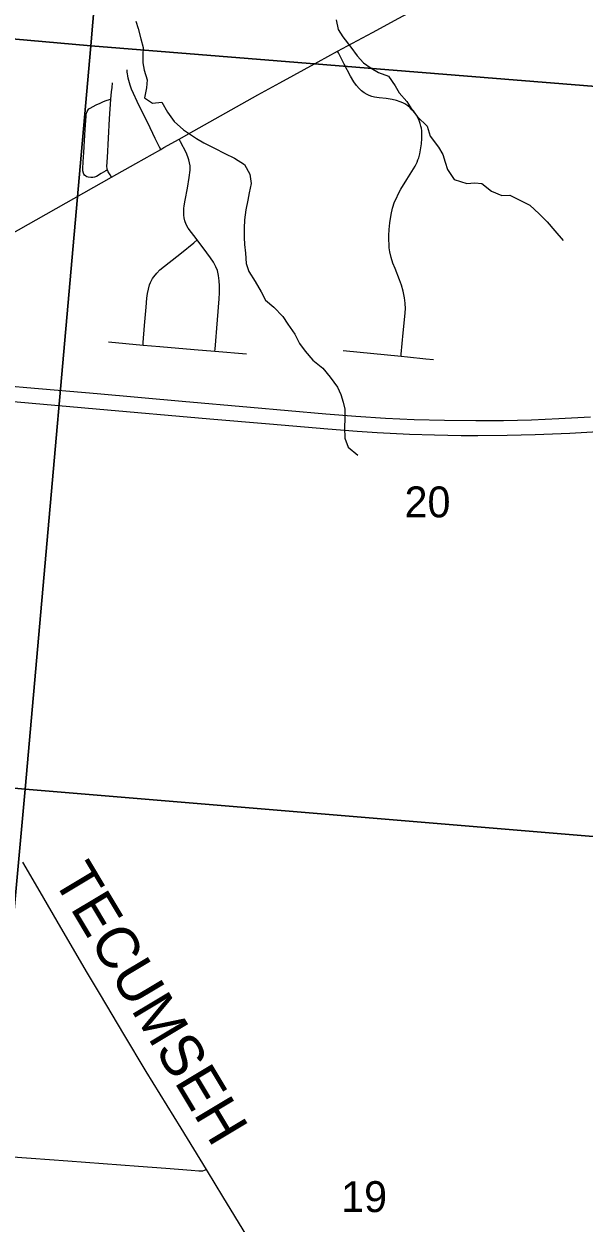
# Model space of a CAD drawing. Extents: x 0 to 34, y 0 to 22.
# Drawn here: x 4.873 to 5.632, y 14.717 to 16.342 of the extents above; entities that cross this region are included whole.
import ezdxf

# ---------------------------------------------------------------- set-up
doc = ezdxf.new("R2010")
doc.units = 0
for name, color, linetype in [('GM_X_County_Road', 7, 'Continuous'), ('GM_X_County_Road_Text', 7, 'Continuous'), ('GM_X_Interstate_Route', 7, 'Continuous'), ('GM_X_Minor_River', 7, 'Continuous'), ('GM_X_Section', 7, 'Continuous'), ('GM_X_Section_Text', 7, 'Continuous'), ('GM_X_Township_Road', 7, 'Continuous')]:
    doc.layers.add(name, color=color, linetype=linetype)

msp = doc.modelspace()

# ---------------------------------------------------------------- linework, layer by layer
at = {"layer": 'GM_X_County_Road'}
for points in [[(5.2978, 16.3047), (5.3453, 16.3303), (5.3808, 16.3494), (5.4408, 16.3822), (5.4842, 16.4065), (5.5036, 16.4175)], [(5.0832, 16.1858), (5.1029, 16.1969), (5.1463, 16.2213), (5.1897, 16.2455), (5.2196, 16.2621), (5.2714, 16.2904), (5.2978, 16.3047)], [(5.0582, 16.1717), (5.0623, 16.1741), (5.0832, 16.1858)], [(4.9914, 16.134), (5.0244, 16.1527), (5.0582, 16.1717)], [(4.6243, 15.9265), (4.652, 15.9425), (4.7017, 15.9701), (4.7345, 15.9885), (4.7768, 16.0126), (4.8276, 16.0414), (4.9914, 16.134)], [(5.1201, 14.7896), (5.0857, 14.8456), (5.0386, 14.9224), (5.0079, 14.9728), (4.9922, 14.9996), (4.9765, 15.0264), (4.9588, 15.0557), (4.9257, 15.1119), (4.8918, 15.1712), (4.8713, 15.206)], [(5.2834, 14.3675), (5.2817, 14.3768), (5.2809, 14.3811), (5.2799, 14.387), (5.2791, 14.3933), (5.2745, 14.4397), (5.2709, 14.4768), (5.268, 14.5046), (5.2659, 14.5201), (5.2641, 14.5293), (5.2617, 14.5383), (5.2601, 14.5434), (5.2586, 14.5472), (5.2561, 14.553), (5.252, 14.5613), (5.24, 14.5832), (5.2296, 14.6022), (5.1983, 14.6594), (5.1845, 14.6838), (5.175, 14.6998), (5.1587, 14.7263), (5.1425, 14.7528), (5.1216, 14.7873), (5.1201, 14.7896)]]:
    msp.add_lwpolyline(points, dxfattribs=at)
at = {"layer": 'GM_X_Interstate_Route'}
for points in [[(4.4694, 15.8846), (4.5389, 15.8785), (4.5509, 15.8774), (4.6352, 15.8704), (4.8152, 15.8545), (4.8766, 15.8491), (4.9718, 15.8409), (5.087, 15.8306), (5.1797, 15.8225), (5.282, 15.8136), (5.3227, 15.8103), (5.3626, 15.8077), (5.4014, 15.806), (5.4428, 15.8049), (5.4852, 15.8044), (5.5227, 15.8046), (5.5606, 15.8054), (5.5978, 15.807), (5.6405, 15.8094)], [(4.4701, 15.8638), (4.5074, 15.8606), (4.5483, 15.8571), (4.639, 15.8493), (4.7133, 15.8429), (4.8636, 15.8295), (4.9707, 15.8203), (5.1248, 15.8069), (5.2055, 15.7999), (5.2844, 15.7931), (5.3244, 15.7899), (5.3512, 15.7881), (5.3951, 15.7859), (5.4291, 15.7849), (5.4653, 15.7843), (5.4878, 15.7839), (5.5274, 15.7845), (5.5654, 15.7855), (5.6127, 15.7873), (5.6507, 15.7897)]]:
    msp.add_lwpolyline(points, dxfattribs=at)
at = {"layer": 'GM_X_Minor_River'}
for points in [[(5.0242, 16.3454), (5.0275, 16.3355), (5.0311, 16.3217), (5.0344, 16.3096), (5.0339, 16.2997), (5.0338, 16.2891), (5.0355, 16.2792), (5.0399, 16.2662), (5.0387, 16.2552), (5.0362, 16.2416), (5.0471, 16.2346), (5.0597, 16.2356), (5.0675, 16.2222), (5.0761, 16.2096), (5.0889, 16.1981), (5.1066, 16.1865), (5.1167, 16.1806), (5.1311, 16.1733), (5.1451, 16.1663), (5.1583, 16.16), (5.1715, 16.1511), (5.1789, 16.1381), (5.1806, 16.1256), (5.1778, 16.1131), (5.1762, 16.1029), (5.1734, 16.09), (5.1717, 16.0763), (5.1712, 16.065), (5.1714, 16.0524), (5.1716, 16.0429), (5.173, 16.0312), (5.174, 16.0171), (5.1773, 16.0064), (5.1862, 15.9927), (5.194, 15.9789), (5.2003, 15.9674), (5.2112, 15.9578), (5.2236, 15.9455), (5.2303, 15.9348), (5.24, 15.9214), (5.246, 15.9088), (5.2538, 15.8985), (5.2643, 15.8862), (5.2778, 15.8754), (5.2879, 15.8631), (5.2977, 15.8494), (5.3021, 15.8398), (5.3054, 15.8291), (5.3075, 15.8196), (5.3078, 15.8071), (5.3072, 15.7949), (5.3078, 15.7805), (5.3119, 15.7683), (5.325, 15.7575)], [(5.2958, 16.3471), (5.2987, 16.3342), (5.305, 16.3242), (5.3159, 16.3104), (5.3245, 16.2986), (5.3327, 16.289), (5.3432, 16.2816), (5.3534, 16.2758), (5.3667, 16.2711), (5.3756, 16.2581), (5.3812, 16.2482), (5.3917, 16.2366), (5.3984, 16.2259), (5.4062, 16.216), (5.419, 16.2033), (5.4234, 16.1896), (5.4346, 16.175), (5.4402, 16.1647), (5.4435, 16.1544), (5.4468, 16.1445), (5.4557, 16.1311), (5.4731, 16.1256), (5.4838, 16.1266), (5.4933, 16.1254), (5.5064, 16.1153), (5.5204, 16.1095), (5.5314, 16.1097), (5.5458, 16.1027), (5.5582, 16.0961), (5.571, 16.0846), (5.5819, 16.0734), (5.5924, 16.0612), (5.6036, 16.0481)]]:
    msp.add_lwpolyline(points, dxfattribs=at)
at = {"layer": 'GM_X_Section'}
for points in [[(4.0957, 17.4007), (5.0487, 17.3219), (4.9634, 16.3122), (4.0036, 16.3979)], [(5.0487, 17.3219), (6.0711, 17.2462), (5.9902, 16.2292), (4.9634, 16.3122)], [(4.0036, 16.3979), (4.9634, 16.3122), (4.8743, 15.3051), (3.89, 15.3957)], [(4.9634, 16.3122), (5.9902, 16.2292), (5.8825, 15.2209), (4.8743, 15.3051)], [(3.89, 15.3957), (4.8743, 15.3051), (4.7835, 14.3098), (3.8021, 14.3916), (3.7885, 14.3929)], [(4.8743, 15.3051), (5.8825, 15.2209), (5.7982, 14.227), (4.7952, 14.3092), (4.7835, 14.3098)]]:
    msp.add_lwpolyline(points, close=True, dxfattribs=at)
at = {"layer": 'GM_X_Township_Road'}
for p, q in [((4.9875, 15.9108), (5.0343, 15.9067)), ((5.1314, 15.8983), (5.1745, 15.8948)), ((5.3053, 15.8994), (5.3838, 15.8914))]:
    msp.add_line(p, q, dxfattribs=at)
for points in [[(5.3838, 15.8914), (5.3841, 15.8941), (5.3868, 15.9233), (5.389, 15.9455), (5.3896, 15.9557), (5.3892, 15.9634), (5.3886, 15.9707), (5.3867, 15.9796), (5.3842, 15.988), (5.3818, 15.9952), (5.3756, 16.0106), (5.3728, 16.0178), (5.3702, 16.0255), (5.3686, 16.0329), (5.3679, 16.0382), (5.3676, 16.0421), (5.3672, 16.05), (5.3672, 16.0553), (5.3679, 16.0631), (5.3688, 16.0722), (5.3705, 16.0837), (5.3724, 16.092), (5.3751, 16.1006), (5.3774, 16.1057), (5.3799, 16.1112), (5.3835, 16.1177), (5.3915, 16.1308), (5.4028, 16.149), (5.4057, 16.1545), (5.4066, 16.1574), (5.4077, 16.1604), (5.4091, 16.1656), (5.4103, 16.1711), (5.4113, 16.1792), (5.4118, 16.1865), (5.4121, 16.1914), (5.4118, 16.1968), (5.4114, 16.2004), (5.4107, 16.2034), (5.4099, 16.2068), (5.409, 16.2095), (5.4079, 16.2123), (5.4062, 16.2155), (5.4046, 16.218), (5.4027, 16.2208), (5.4009, 16.2229), (5.3986, 16.2255), (5.3963, 16.2281), (5.3929, 16.231), (5.3891, 16.2333), (5.3864, 16.2349), (5.3828, 16.2364), (5.3778, 16.238), (5.3718, 16.2392), (5.3637, 16.2405), (5.3539, 16.2416), (5.3478, 16.2426), (5.3442, 16.2436), (5.3407, 16.245), (5.3377, 16.2463), (5.334, 16.2485), (5.3304, 16.2512), (5.3271, 16.2542), (5.3232, 16.2584), (5.3198, 16.2634), (5.3154, 16.2708), (5.3068, 16.2871), (5.299, 16.3025), (5.2978, 16.3047)], [(5.0582, 16.1717), (5.0566, 16.175), (5.0508, 16.1867), (5.0405, 16.2078), (5.0291, 16.2309), (5.0187, 16.2533), (5.0165, 16.2587), (5.0147, 16.2652), (5.0141, 16.2684), (5.0135, 16.2713), (5.0131, 16.274), (5.0128, 16.2762), (5.0126, 16.2782), (5.0125, 16.2794)], [(4.9904, 16.24), (4.9915, 16.2497), (4.9922, 16.2558), (4.9928, 16.2618)], [(4.9859, 16.1441), (4.9835, 16.1426), (4.9776, 16.1389), (4.971, 16.1351), (4.9684, 16.134), (4.9661, 16.1336), (4.9632, 16.1336), (4.96, 16.134), (4.958, 16.1345), (4.9564, 16.1353), (4.9548, 16.1367), (4.9538, 16.138), (4.9533, 16.1396), (4.9527, 16.1427), (4.9526, 16.1458), (4.9529, 16.1551), (4.9538, 16.1676), (4.9547, 16.1832), (4.9558, 16.1988), (4.957, 16.217), (4.9573, 16.2195), (4.9583, 16.2232), (4.9596, 16.2254), (4.9609, 16.2267), (4.9625, 16.2277), (4.9664, 16.2298), (4.9707, 16.232), (4.9759, 16.2345), (4.9804, 16.2366), (4.9842, 16.238), (4.9885, 16.2395), (4.9904, 16.24)], [(4.9859, 16.1441), (4.9856, 16.1457), (4.9853, 16.1488), (4.9858, 16.1609), (4.9889, 16.213), (4.9904, 16.24)], [(5.1075, 16.0491), (5.0953, 16.065), (5.0928, 16.0702), (5.0909, 16.0748), (5.0897, 16.0789), (5.0892, 16.0828), (5.0892, 16.0865), (5.0895, 16.0916), (5.0899, 16.0955), (5.0912, 16.103), (5.0943, 16.1191), (5.0968, 16.1337), (5.0979, 16.1434), (5.0979, 16.1495), (5.0972, 16.1536), (5.0963, 16.1575), (5.0948, 16.1619), (5.0926, 16.1674), (5.0851, 16.182), (5.0832, 16.1858)], [(4.9914, 16.134), (4.9895, 16.1371), (4.9871, 16.1413), (4.9864, 16.1428), (4.9859, 16.1441)], [(5.0343, 15.9067), (5.0345, 15.9099), (5.0362, 15.9333), (5.0385, 15.9579), (5.0395, 15.9702), (5.0403, 15.9763), (5.0414, 15.9824), (5.0431, 15.9884), (5.0442, 15.9912), (5.0455, 15.994), (5.0471, 15.9967), (5.0488, 15.9993), (5.0527, 16.0041), (5.0571, 16.0084), (5.0861, 16.0316), (5.1028, 16.0453), (5.1075, 16.0491)], [(5.1314, 15.8983), (5.1317, 15.9013), (5.135, 15.9406), (5.1374, 15.9692), (5.1376, 15.9772), (5.1379, 15.9867), (5.1374, 15.9938), (5.1364, 16.0011), (5.1349, 16.0076), (5.1328, 16.0125), (5.1296, 16.0189), (5.1257, 16.0249), (5.1208, 16.0318), (5.1075, 16.0491)], [(5.0343, 15.9067), (5.0571, 15.9047), (5.1035, 15.9006), (5.1314, 15.8983)], [(5.3838, 15.8914), (5.3925, 15.8906), (5.4174, 15.8881), (5.4276, 15.8873)], [(4.8516, 14.8072), (4.8826, 14.805), (4.9321, 14.8013), (5.0281, 14.794), (5.0652, 14.7912), (5.0992, 14.7887), (5.1096, 14.7878), (5.1127, 14.7876), (5.1153, 14.7879), (5.1176, 14.7887), (5.1201, 14.7896)]]:
    msp.add_lwpolyline(points, dxfattribs=at)

# ---------------------------------------------------------------- texts
at = {"layer": 'GM_X_County_Road_Text'}
msp.add_text('TECUMSEH', height=0.05682, rotation=300.9211, dxfattribs=at).set_placement((4.9109, 15.1837))
at = {"layer": 'GM_X_Section_Text'}
for s, p in [('20', (5.3885, 15.6732)), ('19', (5.3026, 14.7319))]:
    msp.add_text(s, height=0.04186, rotation=0, dxfattribs=at).set_placement(p)

doc.saveas('drawing.dxf')
